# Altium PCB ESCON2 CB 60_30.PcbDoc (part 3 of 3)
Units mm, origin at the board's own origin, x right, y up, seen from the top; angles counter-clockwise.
Board outline 93.5 x 46 mm, 8 copper layers (Top Side, Inner Layer 1, Inner Layer 2, Inner Layer 3, Inner Layer 4, Inner Layer 5, Inner Layer 6, Bottom Side), stack 1.485 mm thick; 144 components, 77 nets, 473 pads, 3049 vias.
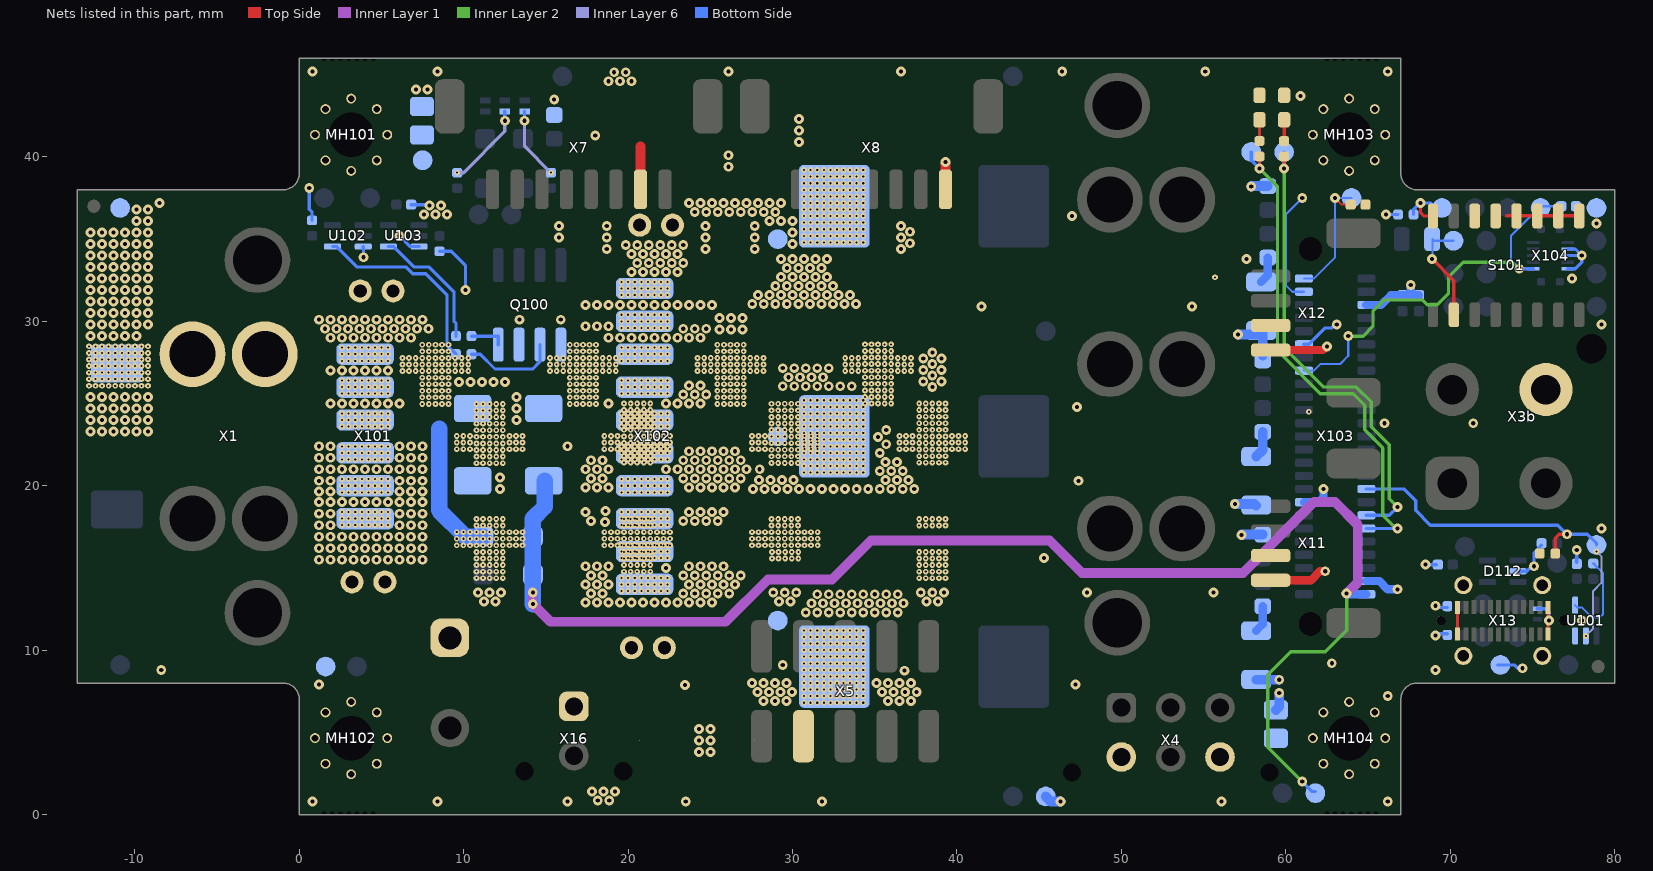
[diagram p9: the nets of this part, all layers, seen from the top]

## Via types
v1: diameter 0.35, hole 0.125, Inner Layer 6 to Bottom Side, tented both sides, 1246 vias
v2: diameter 0.6, hole 0.25, Top Side to Bottom Side, 953 vias
v3: diameter 0.35, hole 0.125, Top Side to Inner Layer 1, tented both sides, 790 vias
v4: diameter 0.6, hole 0.25, Top Side to Bottom Side, tented bottom, 58 vias
v5: diameter 0.6, hole 0.25, Top Side to Bottom Side, tented top, 2 vias

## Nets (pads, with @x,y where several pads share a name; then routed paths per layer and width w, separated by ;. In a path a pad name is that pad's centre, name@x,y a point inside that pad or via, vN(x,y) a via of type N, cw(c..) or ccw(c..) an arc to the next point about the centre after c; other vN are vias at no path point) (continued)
GND: C101.2 C102.2 C103.2 C104.2 C105.2 C106.2 C108.2 C110.2 C112.1 C113.1 C114.1 C115.1 C116.1 C117.1 C118.1 C119.1 C120.2 C121.2 C122.1 C123.1 C124.1 D101.2 D104.2 D106.1 D112.2 D113.1 D114.1 DS101.1 DS102.1 Q100.1 Q100.3 R102.1 R103.1 R105.1 R107.2 R108.2 R117.1 R118.1 R119.1 R120.1 R121.1 S101.1 S101.2 S101.3 S101.4 S101.5 S101.6 TP101.1 TP116.1 TP125.1 TP149.1 U101.3 U102.3 U103.3 X1.1 X2.1 X4.4 X5.3 X7.7 X8.7 X11.3 X12.3 X13.A1 X13.A12 X13.B1 X13.B12 X16.1 X101.0a X101.1 X101.2 X101.3 X103.3 X103.16 X103.40 X103.45 X104.3 X104.5 X104.9 | length 54.3
  Top Side w0.2: X13.A12@70.45,10.965 X13.A12@70.45,10.995 X13.B1@70.45,12.605 X13.B1@70.45,12.635 ; 73.425,36.425 76.575,36.425 77.827,36.425 S101.1@77.845,36.407 ; X13.A1@75.95,10.965 X13.A1@75.95,10.995 X13.B12@75.95,12.605 X13.B12@75.95,12.635
  Top Side w0.6: X7.7@20.75,38.025 20.75,40.65 ; X8.7@39.3,37.925 X8.7@39.3,38.025 v2@39.3,39.6
  Bottom Side w0.2: v2(0.6,38.1) 0.6,36.825 0.775,36.65 R119.1@0.775,36.14 ; U102.3@3.885,34.55 3.885,34.365 3.9,34.35 v2(3.9,33.9) ; v2(6.1,35.2) 6.75,34.55 U103.3@7.285,34.55 ; C122.1@6.8,37.1 v2@8,37.1 ; R120.1@8.525,34.255 9.245,34.255 10.1,33.4 v2(10.1,31.9) ; X103.40@61.1,28.6 61.4,28.6 62.4,29.6 62.8,29.6 63,29.8 v2(63.1,29.8) ; v2(66.1,36.5) R117.1@66.83,36.5 ; v2(68.5,15.2) C112.1@69.15,15.2 ; v2@69.1,11 R108.2@69.83,11 ; v2@69.1,12.6 R107.2@69.83,12.6 ; TP116.1@72.9,9.1 TP116.1@73.05,9.1 73.9,9.1 74.1,8.9 v2(74.4,8.9) ; D112.2@74.135,14.8 74.655,14.8 74.955,15.1 v2(75.1,15.1) 75.1,15.94 R118.1@75.56,16.4 ; D106.1@75.3,12.525 75.775,12.525 76,12.3 v2(76,11.8) ; X104.9@77.145,33.2 77.6,33.2 78,33.6 v2(78,34) ; X104.5@77.145,34 77.53,34 v2(78,34) ; X104.3@77.145,34.4 77.6,34.4 v2(78,34) ; C116.1@77.7,15.35 v2(77.7,16.1)
  Bottom Side w0.5: X103.16@61.1,19 62,19 62.3,19.3 v2(62.3,19.8) ; X103.3@64.9,14.2 65.7,14.2 66.2,13.7 v2(66.8,13.7) ; X103.45@64.9,31 65.45,31 65.8,31 66.385,31.585 D114.1@67.1,31.585 D113.1@68.1,31.585 67.6,31.585 v2(67.6,32.2)
  Bottom Side w0.6: TP125.1@45.4,1.1 45.7,0.8 v4(46.3,0.8) ; v2@56.912,18.888 58.108,18.888 R103.1@58.188,18.808 ; v2(57.1,29.2) 58.26,29.2 R105.1@58.5,29.44 58.6,29.34 C114.1@58.6,27.925 ; v2@57.325,17.025 C113.1@58.6,17.025 ; v2(57.9,38.2) 57.925,38.225 C115.1@58.9,38.225 ; R102.1@58.22,8.2 v2(59.6,8.2) ; C118.1@59.4,6.365 59.6,6.565 v2(59.6,7.4)
  other v1: 2.6,17.6 3,17.6 3.4,17.6 3.8,17.6 4.2,17.6 4.6,17.6 5,17.6 5.4,17.6 2.6,18 3,18 3.4,18 3.8,18 4.2,18 4.6,18 5,18 5.4,18 2.6,18.4 3,18.4 3.4,18.4 3.8,18.4 4.2,18.4 4.6,18.4 5,18.4 5.4,18.4 2.6,19.6 3,19.6 3.4,19.6 3.8,19.6 4.2,19.6 4.6,19.6 5,19.6 5.4,19.6 2.6,20 3,20 3.4,20 3.8,20 4.2,20 4.6,20 5,20 5.4,20 2.6,20.4 3,20.4 3.4,20.4 3.8,20.4 4.2,20.4 4.6,20.4 5,20.4 5.4,20.4 2.6,21.6 3,21.6 3.4,21.6 3.8,21.6 4.2,21.6 4.6,21.6 5,21.6 5.4,21.6 2.6,22 3,22 3.4,22 3.8,22 4.2,22 4.6,22 5,22 5.4,22 2.6,22.4 3,22.4 3.4,22.4 3.8,22.4 4.2,22.4 4.6,22.4 5,22.4 5.4,22.4
  other v2: 0.8,0.8 8.4,0.8 16.3,0.8 23.5,0.8 31.8,0.8 56.1,0.8 66.2,0.8 24.3,3.8 25,3.8 24.3,4.5 25,4.5 24.3,5.2 25,5.2 66.2,7.2 23.463,7.871 1.2,7.9 47.2,7.9 36.8,8.75 -8.4,8.8 69.1,8.8 29.4,9.1 62.8,9.2 69.1,10.9 78,11.8 69.1,12.7 11.225,12.95 11.925,12.95 29.175,12.95 29.875,12.95 38.15,12.95 38.85,12.95 10.875,13.5 11.575,13.5 12.275,13.5 28.825,13.5 29.525,13.5 30.225,13.5 37.8,13.5 38.5,13.5 39.2,13.5 47.9,13.5 55.6,13.5 1.2,15.5 1.9,15.5 2.6,15.5 3.3,15.5 4,15.5 4.7,15.5 5.4,15.5 6.1,15.5 6.8,15.5 7.5,15.5 45.3,15.6 1.2,16.2 1.9,16.2 2.6,16.2 3.3,16.2 4,16.2 4.7,16.2 5.4,16.2 6.1,16.2 6.8,16.2 7.5,16.2 1.2,16.9 1.9,16.9 2.6,16.9 3.3,16.9 4,16.9 4.7,16.9 5.4,16.9 6.1,16.9 6.8,16.9 7.5,16.9 57.3,17 79.2,17.4 1.2,17.6 6.8,17.6 7.5,17.6 18.6,17.8 1.2,18.3 6.8,18.3 7.5,18.3 18.626,18.462 56.9,18.9 1.2,19 1.9,19 6.1,19 6.8,19 7.5,19 1.2,19.65 6.8,19.65 7.5,19.65 12.2,19.8 1.2,20.3 6.8,20.3 7.5,20.3 47.4,20.3 12.2,20.5 1.2,21 6.1,21 6.8,21 7.5,21 1.2,21.7 6.8,21.7 7.5,21.7 1.2,22.4 6.8,22.4 7.5,22.4 16.3,22.4 66,23.8 71.4,23.8 13.2,24 13.2,24.7 47.3,24.8 13.2,25.4 79.2,29.8 13.4,30.1 15.9,30.1 41.5,30.9 54.3,30.9 77.4,32.6 57.6,33.8 18.7,34.4 24.7,34.4 27.7,34.4 36.6,34.4 37.15,34.75 15.8,35.1 18.7,35.1 24.7,35.1 27.7,35.1 36.6,35.1 37.15,35.45 15.8,35.8 18.7,35.8 24.7,35.8 27.7,35.8 36.6,35.8 47,36.4 7.575,36.5 8.275,36.5 8.975,36.5 7.925,37.05 8.625,37.05 -8.5,37.2 26.1,39.4 39.3,39.7 26.1,40.1 30.4,40.9 18,41.3 30.4,41.6 30.4,42.3 15.5,43.5 60.9,43.7 7.1,44.1 7.8,44.1 0.8,45.2 8.4,45.2 26.1,45.2 36.6,45.2 46.4,45.2 55.1,45.2 66.2,45.2
  other v3: 10.775,14.375 11.175,14.375 11.575,14.375 11.975,14.375 12.375,14.375 37.7,14.375 38.1,14.375 38.5,14.375 38.9,14.375 39.3,14.375 10.775,14.775 11.175,14.775 11.575,14.775 11.975,14.775 12.375,14.775 19.75,14.775 20.15,14.775 20.55,14.775 20.95,14.775 21.35,14.775 37.7,14.775 38.1,14.775 38.5,14.775 38.9,14.775 39.3,14.775 10.775,15.175 11.175,15.175 11.575,15.175 11.975,15.175 12.375,15.175 19.75,15.175 20.15,15.175 20.55,15.175 20.95,15.175 21.35,15.175 37.7,15.175 38.1,15.175 38.5,15.175 38.9,15.175 39.3,15.175 10.775,15.575 11.175,15.575 11.575,15.575 11.975,15.575 12.375,15.575 19.75,15.575 20.15,15.575 20.55,15.575 20.95,15.575 21.35,15.575 28.75,15.575 29.15,15.575 29.55,15.575 29.95,15.575 30.35,15.575 37.7,15.575 38.1,15.575 38.5,15.575 38.9,15.575 39.3,15.575 10.775,15.975 11.175,15.975 11.575,15.975 11.975,15.975 12.375,15.975 19.75,15.975 20.15,15.975 20.55,15.975 20.95,15.975 21.35,15.975 28.75,15.975 29.15,15.975 29.55,15.975 29.95,15.975 30.35,15.975 37.7,15.975 38.1,15.975 38.5,15.975 38.9,15.975 39.3,15.975 9.575,16.375 9.975,16.375 10.375,16.375 10.775,16.375 11.175,16.375 11.575,16.375 11.975,16.375 12.375,16.375 12.775,16.375 13.175,16.375 13.575,16.375 18.55,16.375 18.95,16.375 19.35,16.375 19.75,16.375 20.15,16.375 20.55,16.375 20.95,16.375 21.35,16.375 21.75,16.375 22.15,16.375 22.55,16.375 27.525,16.375 27.925,16.375 28.325,16.375 28.725,16.375 29.125,16.375 29.525,16.375 29.925,16.375 30.325,16.375 30.725,16.375 31.125,16.375 31.525,16.375 9.575,16.775 9.975,16.775 10.375,16.775 10.775,16.775 11.175,16.775 11.575,16.775 11.975,16.775 12.375,16.775 12.775,16.775 13.175,16.775 13.575,16.775 18.55,16.775 18.95,16.775 19.35,16.775 19.75,16.775 20.15,16.775 20.55,16.775 20.95,16.775 21.35,16.775 21.75,16.775 22.15,16.775 22.55,16.775 27.525,16.775 27.925,16.775 28.325,16.775 28.725,16.775 29.125,16.775 29.525,16.775 29.925,16.775 30.325,16.775 30.725,16.775 31.125,16.775 31.525,16.775 9.575,17.175 9.975,17.175 10.375,17.175 10.775,17.175 11.175,17.175 11.575,17.175 11.975,17.175 12.375,17.175 12.775,17.175 13.175,17.175 13.575,17.175 18.55,17.175 18.95,17.175 19.35,17.175 19.75,17.175 20.15,17.175 20.55,17.175 20.95,17.175 21.35,17.175 21.75,17.175 22.15,17.175 22.55,17.175 27.525,17.175 27.925,17.175 28.325,17.175 28.725,17.175 29.125,17.175 29.525,17.175 29.925,17.175 30.325,17.175 30.725,17.175 31.125,17.175 31.525,17.175 10.775,17.575 11.175,17.575 11.575,17.575 11.975,17.575 12.375,17.575 19.75,17.575 20.15,17.575 20.55,17.575 20.95,17.575 21.35,17.575 28.725,17.575 29.125,17.575 29.525,17.575 29.925,17.575 30.325,17.575 37.7,17.575 38.1,17.575 38.5,17.575 38.9,17.575 39.3,17.575 10.775,17.975 11.175,17.975 11.575,17.975 11.975,17.975 12.375,17.975 19.75,17.975 20.15,17.975 20.55,17.975 20.95,17.975 21.35,17.975 28.725,17.975 29.125,17.975 29.525,17.975 29.925,17.975 30.325,17.975 37.7,17.975 38.1,17.975 38.5,17.975 38.9,17.975 39.3,17.975 61.4,24.5 55.7,32.675
  other v4: 1.9,17.6 6.1,17.6 1.9,18.3 6.1,18.3 2.6,19 3.3,19 4,19 4.7,19 5.4,19 1.9,19.65 6.1,19.65 1.9,20.3 6.1,20.3 1.9,21 2.6,21 3.3,21 4,21 4.7,21 5.4,21 1.9,21.7 6.1,21.7 1.9,22.4 6.1,22.4 78.9,35.95
LED_Axis_gn: R110.1 TP142.1 X103.13 | length 28.5
  Top Side w0.2: v2(59.9,39.3) R110.1@59.9,40.03
  Inner Layer 2 w0.2: v2(59.9,39.3) 59.9,28.4 62.3,26 64.3,26 65.2,25.1 65.2,23.6 66.3,22.5 66.3,19.2 v2(66.8,18.7)
  Bottom Side w0.2: v2(59.9,39.3) TP142.1@59.9,40.3 ; X103.13@64.9,18.2 66.3,18.2 v2(66.8,18.7)
LED_Axis_rd: R109.1 TP141.1 X103.11 | length 30.4
  Top Side w0.2: v2(58.4,39.3) R109.1@58.4,40.03
  Inner Layer 2 w0.2: v2(58.4,39.3) 59.5,38.2 59.5,28.2 62.1,25.6 64.1,25.6 64.8,24.9 64.8,23.4 65.9,22.3 65.9,18.2 66.7,17.4 v2(66.8,17.4)
  Bottom Side w0.2: TP141.1@57.9,40.3 57.9,39.8 v2(58.4,39.3) ; X103.11@64.9,17.4 v2(66.8,17.4)
NetC107_1: C107.1 R102.2 | length 1.7
  Bottom Side w0.5: R102.2@58.2,11.18 58.6,11.58 C107.1@58.6,12.675
NetC109_1: C109.1 R103.2 | length 1.7
  Bottom Side w0.6: R103.2@58.2,21.78 58.6,22.18 C109.1@58.6,23.275
NetC111_1: C111.1 R105.2 | length 1.6
  Bottom Side w0.5: R105.2@58.5,32.4 58.9,32.8 C111.1@58.9,33.875
NetD108_1: D108.1 R115.2 | length 4.4
  Inner Layer 6 w0.2: v2(13.7,42.2) 13.7,40.64 v1(15.3,39.04)
  Bottom Side w0.2: v2(13.7,42.2) D108.1@13.7,42.775
NetD109_1: D109.1 R116.2 | length 5.2
  Inner Layer 6 w0.2: v1(9.6,39.04) 9.99,39.04 12.5,41.55 v2(12.5,42.2)
  Bottom Side w0.2: v2(12.5,42.2) D109.1@12.5,42.775
NetDS101_2: DS101.2 R109.2 | length 1.3
  Top Side w0.2: R109.2@58.4,40.97 58.4,41.265 DS101.2@58.4,42.255
NetDS102_2: DS102.2 R110.2 | length 1.3
  Top Side w0.2: R110.2@59.9,40.97 59.9,41.265 DS102.2@59.9,42.255
NetQ100_2: Q100.2 R112.2 | length 5.8
  Bottom Side w0.2: R112.2@10.47,28 11,28 11.9,27.1 14.19,27.1 14.635,27.545 Q100.2@14.635,28.58
NetQ100_4: Q100.4 R114.2 | length 2.1
  Bottom Side w0.2: R114.2@10.47,29.1 12.095,29.1 Q100.4@12.095,28.58
NetR104_1: R104.1 S101.10 TP132.1 | length 6.5
  Top Side w0.2: v2(68.9,33.8) 70.225,32.475 S101.10@70.225,30.393
  Bottom Side w0.125: v2(68.9,33.8) 68.925,33.825 68.925,35 69.025,34.9 TP132.1@70.2,34.9
NetR111_2: R111.2 U101.4 | length 5.4
  Bottom Side w0.125: U101.4@77.6,12.735 77.6,12.721 77.72,12.601 78.003,12.601 78.604,12 79.1,12 79.3,12.2 79.3,14.67 R111.2@78.731,15.239 ; R111.2@78.7,15.27 R111.2@78.763,15.27
NetR112_1: R112.1 U102.4 | length 12
  Bottom Side w0.2: U102.4@2.015,34.55 2.275,34.55 3.525,33.3 6.5,33.3 6.9,32.9 7.7,32.9 8.975,31.625 8.975,28.555 R112.1@9.53,28
NetR114_1: R114.1 U103.4 | length 7.9
  Bottom Side w0.2: U103.4@5.415,34.55 5.75,34.55 7,33.3 7.9,33.3 9.4,31.8 9.4,30 9.53,29.87 R114.1@9.53,29.1
NetR117_2: R117.2 S101.8 TP134.1 | length 3.4
  Top Side w0.2: v2(68.2,37.2) 68.2,36.6 68.393,36.407 S101.8@68.955,36.407
  Bottom Side w0.2: R117.2@67.77,36.5 67.77,36.81 68.16,37.2 v2(68.2,37.2) 68.8,37.2 TP134.1@69.1,36.9
S2_Clock: R121.2 TP144.1 U101.2 X103.17 | length 23.2
  Top Side w0.2: R121.2@76.395,15.875 76.395,16.82 76.625,17.05 v2(77.1,17.05)
  Inner Layer 6 w0.125: v1(78.25,10.865) 78.7,11.315 78.7,13.6 79.2,14.1 79.2,15.7 v1(78.9,16)
  Bottom Side w0.2: X103.17@64.9,19.8 67.2,19.8 67.9,19.1 67.9,18.5 68.8,17.6 76.55,17.6 v2(77.1,17.05) 78.35,17.05 78.9,16.5 TP144.1@78.9,16.4
SGND: C117.2 C118.2 MH101.2 MH101.3 MH101.4 MH101.5 MH101.6 MH101.7 MH101.8 MH101.9 MH102.2 MH102.3 MH102.4 MH102.5 MH102.6 MH102.7 MH102.8 MH102.9 MH103.2 MH103.3 MH103.4 MH103.5 MH103.6 MH103.7 MH103.8 MH103.9 MH104.2 MH104.3 MH104.4 MH104.5 MH104.6 MH104.7 MH104.8 MH104.9 TP153.1 X3b.4 X4.6 X11.4 X12.4 X13.S1 X13.S2 X13.S3 X13.S4 | length 7.2
  Top Side w0.5: X11.4@59.025,14.25 61.525,14.25 62.075,14.8 v2(62.4,14.8) ; X12.4@59.025,28.25 62.25,28.25 v2@62.5,28.5
  other v2: 62.5,28.475
SYS_/Reset: C123.2 TP154.1 X103.36 X104.10 | length 24.9
  Inner Layer 2 w0.2: v2(63.8,29.1) 64.7,29.1 65.3,29.7 65.3,30.6 66,31.3 68.3,31.3 68.6,31 69.2,31 69.9,31.7 69.9,32.7 70.8,33.6 73.8,33.6 v2(74.2,33.2)
  Bottom Side w0.125: X103.36@61.1,27 61.7,27 62.1,27.4 63.3,27.4 63.8,27.9 v2(63.8,29.1) ; v2(74.2,33.2) 73.7,33.7 73.7,35.207 TP154.1@75.446,36.954 ; TP154.1@75.5,36.9 75.6,37 C123.2@76.75,37
  Bottom Side w0.2: v2(74.2,33.2) X104.10@75.055,33.2
U: L101.2 TP138.1 X102.0a X102.1 X102.2 X102.3
  other v1: 30.7,6.8 31.1,6.8 31.5,6.8 31.9,6.8 32.3,6.8 32.7,6.8 33.1,6.8 33.5,6.8 33.9,6.8 34.3,6.8 30.7,7.2 31.1,7.2 31.5,7.2 31.9,7.2 32.3,7.2 32.7,7.2 33.1,7.2 33.5,7.2 33.9,7.2 34.3,7.2 30.7,7.6 31.1,7.6 31.5,7.6 31.9,7.6 32.3,7.6 32.7,7.6 33.1,7.6 33.5,7.6 33.9,7.6 34.3,7.6 30.7,8 31.1,8 31.5,8 31.9,8 32.3,8 32.7,8 33.1,8 33.5,8 33.9,8 34.3,8 30.7,8.4 31.1,8.4 31.5,8.4 31.9,8.4 32.3,8.4 32.7,8.4 33.1,8.4 33.5,8.4 33.9,8.4 34.3,8.4 30.7,8.8 31.1,8.8 31.5,8.8 31.9,8.8 32.3,8.8 32.7,8.8 33.1,8.8 33.5,8.8 33.9,8.8 34.3,8.8 30.7,9.2 31.1,9.2 31.5,9.2 31.9,9.2 32.3,9.2 32.7,9.2 33.1,9.2 33.5,9.2 33.9,9.2 34.3,9.2 30.7,9.6 31.1,9.6 31.5,9.6 31.9,9.6 32.3,9.6 32.7,9.6 33.1,9.6 33.5,9.6 33.9,9.6 34.3,9.6 30.7,10 31.1,10 31.5,10 31.9,10 32.3,10 32.7,10 33.1,10 33.5,10 33.9,10 34.3,10 30.7,10.4 31.1,10.4 31.5,10.4 31.9,10.4 32.3,10.4 32.7,10.4 33.1,10.4 33.5,10.4 33.9,10.4 34.3,10.4 30.7,10.8 31.1,10.8 31.5,10.8 31.9,10.8 32.3,10.8 32.7,10.8 33.1,10.8 33.5,10.8 33.9,10.8 34.3,10.8 30.7,11.2 31.1,11.2 31.5,11.2 31.9,11.2 32.3,11.2 32.7,11.2 33.1,11.2 33.5,11.2 33.9,11.2 34.3,11.2 19.6,13.6 20,13.6 20.4,13.6 20.8,13.6 21.2,13.6 21.6,13.6 22,13.6 22.4,13.6 19.6,14 20,14 20.4,14 20.8,14 21.2,14 21.6,14 22,14 22.4,14 19.6,14.4 20,14.4 20.4,14.4 20.8,14.4 21.2,14.4 21.6,14.4 22,14.4 22.4,14.4 19.6,15.6 20,15.6 20.4,15.6 20.8,15.6 21.2,15.6 21.6,15.6 22,15.6 22.4,15.6 19.6,16 20,16 20.4,16 20.8,16 21.2,16 21.6,16 22,16 22.4,16 19.6,16.4 20,16.4 20.4,16.4 20.8,16.4 21.2,16.4 21.6,16.4 22,16.4 22.4,16.4 19.6,17.6 20,17.6 20.4,17.6 20.8,17.6 21.2,17.6 21.6,17.6 22,17.6 22.4,17.6 19.6,18 20,18 20.4,18 20.8,18 21.2,18 21.6,18 22,18 22.4,18 19.6,18.4 20,18.4 20.4,18.4 20.8,18.4 21.2,18.4 21.6,18.4 22,18.4 22.4,18.4
  other v2: 28.225,6.9 28.925,6.9 29.625,6.9 35.8,6.9 36.5,6.9 37.2,6.9 27.875,7.45 28.575,7.45 29.275,7.45 29.975,7.45 35.45,7.45 36.15,7.45 36.85,7.45 37.55,7.45 27.525,8 28.225,8 28.925,8 29.625,8 35.1,8 35.8,8 36.5,8 37.2,8 30.8,12.3 31.5,12.3 32.2,12.3 32.9,12.3 33.6,12.3 34.3,12.3 35,12.3 35.7,12.3 36.4,12.3 31.15,12.85 31.85,12.85 32.55,12.85 33.25,12.85 33.95,12.85 34.65,12.85 35.35,12.85 36.05,12.85 36.75,12.85 17.4,12.9 18.1,12.9 18.8,12.9 19.5,12.9 20.2,12.9 20.9,12.9 21.6,12.9 22.3,12.9 23,12.9 23.7,12.9 24.4,12.9 25.1,12.9 31.5,13.4 32.2,13.4 32.9,13.4 33.6,13.4 34.3,13.4 35,13.4 35.7,13.4 36.4,13.4 17.75,13.45 18.45,13.45 23.35,13.45 24.05,13.45 24.75,13.45 25.45,13.45 26.15,13.45 17.4,14 18.1,14 18.8,14 23.7,14 24.4,14 25.1,14 25.8,14 26.5,14 17.75,14.55 18.45,14.55 23.35,14.55 24.05,14.55 24.75,14.55 25.45,14.55 26.15,14.55 26.85,14.55 17.4,15.1 18.1,15.1 18.8,15.1 23.7,15.1 24.4,15.1 25.1,15.1 25.8,15.1 17.75,17.85 23.35,17.85 24.05,17.85 24.75,17.85 25.45,17.85 17.4,18.4 23.7,18.4 24.4,18.4 25.1,18.4 25.8,18.4
  other v4: 22.3,15
UART_RxD: C124.2 TP155.1 TPM2.1 X103.50 | length 8.2
  Top Side w0.125: v2(63,37.5) 63.4,37.1 C124.2@63.95,37.1
  Bottom Side w0.125: X103.50@61.1,32.6 61.7,32.6 63,33.9 v2(63,37.5) TP155.1@64,37.5
UART_TxD: TPM1.1 X103.48 | length 7
  Bottom Side w0.125: v2(61,37.5) 60,36.5 60,32.2 60.4,31.8 X103.48@61.1,31.8
V: L102.2 TP139.1 X102.4 X102.5 X102.6 X102.7
  other v1: 19.6,19.6 20,19.6 20.4,19.6 20.8,19.6 21.2,19.6 21.6,19.6 22,19.6 22.4,19.6 19.6,20 20,20 20.4,20 20.8,20 21.2,20 21.6,20 22,20 22.4,20 19.6,20.4 20,20.4 20.4,20.4 20.8,20.4 21.2,20.4 21.6,20.4 22,20.4 22.4,20.4 30.7,20.8 31.1,20.8 31.5,20.8 31.9,20.8 32.3,20.8 32.7,20.8 33.1,20.8 33.5,20.8 33.9,20.8 34.3,20.8 30.7,21.2 31.1,21.2 31.5,21.2 31.9,21.2 32.3,21.2 32.7,21.2 33.1,21.2 33.5,21.2 33.9,21.2 34.3,21.2 19.6,21.6 20,21.6 20.4,21.6 20.8,21.6 21.2,21.6 21.6,21.6 22,21.6 22.4,21.6 30.7,21.6 31.1,21.6 31.5,21.6 31.9,21.6 32.3,21.6 32.7,21.6 33.1,21.6 33.5,21.6 33.9,21.6 34.3,21.6 19.6,22 20,22 20.4,22 20.8,22 21.2,22 21.6,22 22,22 22.4,22 30.7,22 31.1,22 31.5,22 31.9,22 32.3,22 32.7,22 33.1,22 33.5,22 33.9,22 34.3,22 19.6,22.4 20,22.4 20.4,22.4 20.8,22.4 21.2,22.4 21.6,22.4 22,22.4 22.4,22.4 30.7,22.4 31.1,22.4 31.5,22.4 31.9,22.4 32.3,22.4 32.7,22.4 33.1,22.4 33.5,22.4 33.9,22.4 34.3,22.4 30.7,22.8 31.1,22.8 31.5,22.8 31.9,22.8 32.3,22.8 32.7,22.8 33.1,22.8 33.5,22.8 33.9,22.8 34.3,22.8 30.7,23.2 31.1,23.2 31.5,23.2 31.9,23.2 32.3,23.2 32.7,23.2 33.1,23.2 33.5,23.2 33.9,23.2 34.3,23.2 19.6,23.6 20,23.6 20.4,23.6 20.8,23.6 21.2,23.6 21.6,23.6 22,23.6 22.4,23.6 30.7,23.6 31.1,23.6 31.5,23.6 31.9,23.6 32.3,23.6 32.7,23.6 33.1,23.6 33.5,23.6 33.9,23.6 34.3,23.6 19.6,24 20,24 20.4,24 20.8,24 21.2,24 21.6,24 22,24 22.4,24 30.7,24 31.1,24 31.5,24 31.9,24 32.3,24 32.7,24 33.1,24 33.5,24 33.9,24 34.3,24 19.6,24.4 20,24.4 20.4,24.4 20.8,24.4 21.2,24.4 21.6,24.4 22,24.4 22.4,24.4 30.7,24.4 31.1,24.4 31.5,24.4 31.9,24.4 32.3,24.4 32.7,24.4 33.1,24.4 33.5,24.4 33.9,24.4 34.3,24.4 30.7,24.8 31.1,24.8 31.5,24.8 31.9,24.8 32.3,24.8 32.7,24.8 33.1,24.8 33.5,24.8 33.9,24.8 34.3,24.8 30.7,25.2 31.1,25.2 31.5,25.2 31.9,25.2 32.3,25.2 32.7,25.2 33.1,25.2 33.5,25.2 33.9,25.2 34.3,25.2 19.6,25.6 20,25.6 20.4,25.6 20.8,25.6 21.2,25.6 21.6,25.6 22,25.6 22.4,25.6 19.6,26 20,26 20.4,26 20.8,26 21.2,26 21.6,26 22,26 22.4,26 19.6,26.4 20,26.4 20.4,26.4 20.8,26.4 21.2,26.4 21.6,26.4 22,26.4 22.4,26.4
  other v2: 27.6,19.8 28.3,19.8 29,19.8 29.7,19.8 30.4,19.8 31.1,19.8 31.8,19.8 32.5,19.8 33.2,19.8 33.9,19.8 34.6,19.8 35.3,19.8 36,19.8 36.7,19.8 37.4,19.8 17.4,19.9 18.1,19.9 18.8,19.9 23.7,19.9 24.4,19.9 25.1,19.9 25.8,19.9 26.5,19.9 27.95,20.35 28.65,20.35 29.35,20.35 30.05,20.35 35.65,20.35 36.35,20.35 37.05,20.35 17.75,20.45 18.45,20.45 23.35,20.45 24.05,20.45 24.75,20.45 25.45,20.45 26.15,20.45 26.85,20.45 35.3,20.9 36,20.9 36.7,20.9 17.4,21 18.1,21 18.8,21 23,21 23.7,21 24.4,21 25.1,21 25.8,21 26.5,21 27.2,21 28,21 35.65,21.45 36.35,21.45 17.75,21.55 18.45,21.55 23.35,21.55 24.05,21.55 24.75,21.55 25.45,21.55 26.15,21.55 26.85,21.55 35.3,22 23.7,22.1 24.4,22.1 25.1,22.1 25.8,22.1 26.5,22.1 35.7,22.525 35.2,22.975 35.7,23.4 18.8,25 23,25 23.7,25 24.4,25 23.35,25.55 24.05,25.55 24.75,25.55 29.4,26.05 30.1,26.05 30.8,26.05 31.5,26.05 32.2,26.05 32.9,26.05 33.6,26.05 23.7,26.1 24.4,26.1 29.75,26.6 30.45,26.6 31.15,26.6 31.85,26.6 29.4,27.15 30.1,27.15 30.8,27.15 31.5,27.15 32.2,27.15
  other v4: 22.3,21 22.3,25
VL: D102.1 D103.1 D104.1 TP106.1 X103.1 | length 86.6
  Inner Layer 1 w0.6: v2(14.2,13.5) v2(14.2,12.8) 15.275,11.725 25.925,11.725 28.5,14.3 32.4,14.3 34.775,16.675 45.625,16.675 47.6,14.7 57.4,14.7 61.7,19 63,19 64.375,17.625 64.375,14.125 v2(63.7,13.45)
  Inner Layer 2 w0.2: v2(61,2) 58.9,4.1 58.9,8.5 60.3,9.9 62.4,9.9 63.7,11.2 v2(63.7,13.45)
  Bottom Side w0.2: v2(61,2) 61.6,1.4 TP106.1@61.8,1.4
  Bottom Side w0.5: v2(63.7,13.45) 63.75,13.4 X103.1@64.9,13.4
  Bottom Side w1: v2(14.2,12.8) v2(14.2,13.5) ; v2@14.205,13.5 D102.1@14.205,14.6 D103.1@14.205,16.9 14.205,18.005 14.92,18.72 D104.1@14.92,20.3
VP: C101.1 C102.1 C103.1 C104.1 C105.1 C106.1 C108.1 C110.1 C120.1 C121.1 D101.1 D103.2 F101.2 TP104.1 X101.0b X101.4 X101.5 X101.6 | length 8.3
  Bottom Side w1: 8.5,23.473 8.5,18.5 10.1,16.9 D103.2@11.195,16.9
  other v1: 2.6,23.6 3,23.6 3.4,23.6 3.8,23.6 4.2,23.6 4.6,23.6 5,23.6 5.4,23.6 2.6,24 3,24 3.4,24 3.8,24 4.2,24 4.6,24 5,24 5.4,24 2.6,24.4 3,24.4 3.4,24.4 3.8,24.4 4.2,24.4 4.6,24.4 5,24.4 5.4,24.4 2.6,25.6 3,25.6 3.4,25.6 3.8,25.6 4.2,25.6 4.6,25.6 5,25.6 5.4,25.6 2.6,26 3,26 3.4,26 3.8,26 4.2,26 4.6,26 5,26 5.4,26 -12.8,26.08 -12.4,26.08 -12,26.08 -11.6,26.08 -11.2,26.08 -10.8,26.08 -10.4,26.08 -10,26.08 -9.6,26.08 -9.2,26.08 2.6,26.4 3,26.4 3.4,26.4 3.8,26.4 4.2,26.4 4.6,26.4 5,26.4 5.4,26.4 -12.8,26.48 -12.4,26.48 -12,26.48 -11.6,26.48 -11.2,26.48 -10.8,26.48 -10.4,26.48 -10,26.48 -9.6,26.48 -9.2,26.48 -12.8,26.88 -12.4,26.88 -12,26.88 -11.6,26.88 -11.2,26.88 -10.8,26.88 -10.4,26.88 -10,26.88 -9.6,26.88 -9.2,26.88 -12.8,27.28 -12.4,27.28 -12,27.28 -11.6,27.28 -11.2,27.28 -10.8,27.28 -10.4,27.28 -10,27.28 -9.6,27.28 -9.2,27.28 2.6,27.6 3,27.6 3.4,27.6 3.8,27.6 4.2,27.6 4.6,27.6 5,27.6 5.4,27.6 -12.8,27.68 -12.4,27.68 -12,27.68 -11.6,27.68 -11.2,27.68 -10.8,27.68 -10.4,27.68 -10,27.68 -9.6,27.68 -9.2,27.68 2.6,28 3,28 3.4,28 3.8,28 4.2,28 4.6,28 5,28 5.4,28 -12.8,28.08 -12.4,28.08 -12,28.08 -11.6,28.08 -11.2,28.08 -10.8,28.08 -10.4,28.08 -10,28.08 -9.6,28.08 -9.2,28.08 2.6,28.4 3,28.4 3.4,28.4 3.8,28.4 4.2,28.4 4.6,28.4 5,28.4 5.4,28.4 -12.8,28.48 -12.4,28.48 -12,28.48 -11.6,28.48 -11.2,28.48 -10.8,28.48 -10.4,28.48 -10,28.48 -9.6,28.48 -9.2,28.48
  other v2: 18.15,0.85 18.85,0.85 17.8,1.4 18.5,1.4 19.2,1.4 -12.7,23.3 -12,23.3 -11.3,23.3 -10.6,23.3 -9.9,23.3 -9.2,23.3 -12.7,24 -12,24 -11.3,24 -10.6,24 -9.9,24 -9.2,24 -12.7,24.7 -12,24.7 -11.3,24.7 -10.6,24.7 -9.9,24.7 -9.2,24.7 1.9,25 6.1,25 -12.7,25.4 -12,25.4 -11.3,25.4 -10.6,25.4 -9.9,25.4 -9.2,25.4 38.5,26 11.1,26.3 11.8,26.3 12.5,26.3 37.95,26.35 39.05,26.35 38.5,26.7 1.9,27 37.95,27.05 39.05,27.05 38.5,27.4 37.95,27.75 39.05,27.75 38.5,28.1 1.9,29 6.1,29 6.8,29 -12.7,29.1 -12,29.1 -11.3,29.1 -10.6,29.1 -9.9,29.1 25.55,29.5 26.25,29.5 26.95,29.5 1.55,29.55 2.25,29.55 2.95,29.55 3.65,29.55 4.35,29.55 5.05,29.55 5.75,29.55 6.45,29.55 7.15,29.55 7.85,29.55 -12.7,29.8 -12,29.8 -11.3,29.8 -10.6,29.8 -9.9,29.8 -9.2,29.8 1.2,30.1 1.9,30.1 2.6,30.1 3.3,30.1 4,30.1 4.7,30.1 5.4,30.1 6.1,30.1 6.8,30.1 7.5,30.1 25.55,30.2 26.25,30.2 26.95,30.2 -12.7,30.5 -12,30.5 -11.3,30.5 -10.6,30.5 -9.9,30.5 -9.2,30.5 -12.7,31.2 -12,31.2 -11.3,31.2 -10.6,31.2 -9.9,31.2 -9.2,31.2 -12.7,31.9 -12,31.9 -11.3,31.9 -10.6,31.9 -9.9,31.9 -9.2,31.9 -12.7,32.6 -12,32.6 -11.3,32.6 -10.6,32.6 -9.9,32.6 -9.2,32.6 -12.7,33.3 -12,33.3 -11.3,33.3 -10.6,33.3 -9.9,33.3 -9.2,33.3 -12.7,34 -12,34 -11.3,34 -10.6,34 -9.9,34 -9.2,34 -12.7,34.7 -12,34.7 -11.3,34.7 -10.6,34.7 -9.9,34.7 -9.2,34.7 -12.7,35.4 -12,35.4 -11.3,35.4 -10.6,35.4 -9.9,35.4 -9.2,35.4 -9.9,36.1 -9.2,36.1 -9.9,36.8 -9.2,36.8 18.8,44.6 19.5,44.6 20.2,44.6 19.15,45.15 19.85,45.15
  other v3: 10.775,21.375 11.175,21.375 11.575,21.375 11.975,21.375 12.375,21.375 19.75,21.4 20.15,21.4 20.55,21.4 20.95,21.4 21.35,21.4 28.724,21.388 29.124,21.388 29.524,21.388 29.924,21.388 30.324,21.388 37.7,21.4 38.1,21.4 38.5,21.4 38.9,21.4 39.3,21.4 10.775,21.775 11.175,21.775 11.575,21.775 11.975,21.775 12.375,21.775 28.724,21.788 29.124,21.788 29.524,21.788 29.924,21.788 30.324,21.788 19.75,21.8 20.15,21.8 20.55,21.8 20.95,21.8 21.35,21.8 37.7,21.8 38.1,21.8 38.5,21.8 38.9,21.8 39.3,21.8 10.775,22.175 11.175,22.175 11.575,22.175 11.975,22.175 12.375,22.175 19.75,22.2 20.15,22.2 20.55,22.2 20.95,22.2 21.35,22.2 28.724,22.188 29.124,22.188 29.524,22.188 29.924,22.188 30.324,22.188 37.7,22.2 38.1,22.2 38.5,22.2 38.9,22.2 39.3,22.2 9.575,22.225 9.975,22.225 10.375,22.225 12.775,22.225 13.175,22.225 13.575,22.225 18.55,22.225 18.95,22.225 19.35,22.225 21.75,22.225 22.15,22.225 22.55,22.225 27.525,22.225 27.925,22.225 28.325,22.225 30.725,22.225 31.125,22.225 31.525,22.225 36.5,22.225 36.9,22.225 37.3,22.225 39.7,22.225 40.1,22.225 40.5,22.225 10.775,22.575 11.175,22.575 11.575,22.575 11.975,22.575 12.375,22.575 19.75,22.6 20.15,22.6 20.55,22.6 20.95,22.6 21.35,22.6 28.724,22.588 29.124,22.588 29.524,22.588 29.924,22.588 30.324,22.588 37.7,22.6 38.1,22.6 38.5,22.6 38.9,22.6 39.3,22.6 9.575,22.625 9.975,22.625 10.375,22.625 12.775,22.625 13.175,22.625 13.575,22.625 18.55,22.625 18.95,22.625 19.35,22.625 21.75,22.625 22.15,22.625 22.55,22.625 27.525,22.625 27.925,22.625 28.325,22.625 30.725,22.625 31.125,22.625 31.525,22.625 36.5,22.625 36.9,22.625 37.3,22.625 39.7,22.625 40.1,22.625 40.5,22.625 10.775,22.975 11.175,22.975 11.575,22.975 11.975,22.975 12.375,22.975 19.75,23 20.15,23 20.55,23 20.95,23 21.35,23 28.724,22.988 29.124,22.988 29.524,22.988 29.924,22.988 30.324,22.988 37.7,23 38.1,23 38.5,23 38.9,23 39.3,23 9.575,23.025 9.975,23.025 10.375,23.025 12.775,23.025 13.175,23.025 13.575,23.025 18.55,23.025 18.95,23.025 19.35,23.025 21.75,23.025 22.15,23.025 22.55,23.025 27.525,23.025 27.925,23.025 28.325,23.025 30.725,23.025 31.125,23.025 31.525,23.025 36.5,23.025 36.9,23.025 37.3,23.025 39.7,23.025 40.1,23.025 40.5,23.025 10.775,23.375 11.175,23.375 11.575,23.375 11.975,23.375 12.375,23.375 28.724,23.388 29.124,23.388 29.524,23.388 29.924,23.388 30.324,23.388 19.75,23.4 20.15,23.4 20.55,23.4 20.95,23.4 21.35,23.4 37.7,23.4 38.1,23.4 38.5,23.4 38.9,23.4 39.3,23.4 10.775,23.775 11.175,23.775 11.575,23.775 11.975,23.775 12.375,23.775 19.75,23.8 20.15,23.8 20.55,23.8 20.95,23.8 21.35,23.8 28.724,23.788 29.124,23.788 29.524,23.788 29.924,23.788 30.324,23.788 37.7,23.8 38.1,23.8 38.5,23.8 38.9,23.8 39.3,23.8 10.775,24.175 11.175,24.175 11.575,24.175 11.975,24.175 12.375,24.175 19.75,24.2 20.15,24.2 20.55,24.2 20.95,24.2 21.35,24.2 28.724,24.188 29.124,24.188 29.524,24.188 29.924,24.188 30.324,24.188 37.7,24.2 38.1,24.2 38.5,24.2 38.9,24.2 39.3,24.2 10.775,24.575 11.175,24.575 11.575,24.575 11.975,24.575 12.375,24.575 19.75,24.6 20.15,24.6 20.55,24.6 20.95,24.6 21.35,24.6 28.724,24.588 29.124,24.588 29.524,24.588 29.924,24.588 30.324,24.588 37.7,24.6 38.1,24.6 38.5,24.6 38.9,24.6 39.3,24.6 7.475,24.975 7.875,24.975 8.275,24.975 8.675,24.975 9.075,24.975 10.775,24.975 11.175,24.975 11.575,24.975 11.975,24.975 12.375,24.975 16.45,24.975 16.85,24.975 17.25,24.975 17.65,24.975 18.05,24.975 25.425,24.975 25.825,24.975 26.225,24.975 26.625,24.975 27.025,24.975 28.724,24.988 29.124,24.988 29.524,24.988 29.924,24.988 30.324,24.988 19.75,25 20.15,25 20.55,25 20.95,25 21.35,25 34.4,25 34.8,25 35.2,25 35.6,25 36,25 37.7,25 38.1,25 38.5,25 38.9,25 39.3,25 7.475,25.375 7.875,25.375 8.275,25.375 8.675,25.375 9.075,25.375 16.45,25.375 16.85,25.375 17.25,25.375 17.65,25.375 18.05,25.375 25.425,25.375 25.825,25.375 26.225,25.375 26.625,25.375 27.025,25.375 34.4,25.4 34.8,25.4 35.2,25.4 35.6,25.4 36,25.4 7.475,25.775 7.875,25.775 8.275,25.775 8.675,25.775 9.075,25.775 16.45,25.775 16.85,25.775 17.25,25.775 17.65,25.775 18.05,25.775 25.425,25.775 25.825,25.775 26.225,25.775 26.625,25.775 27.025,25.775 34.4,25.8 34.8,25.8 35.2,25.8 35.6,25.8 36,25.8 7.475,26.175 7.875,26.175 8.275,26.175 8.675,26.175 9.075,26.175 16.45,26.175 16.85,26.175 17.25,26.175 17.65,26.175 18.05,26.175 25.425,26.175 25.825,26.175 26.225,26.175 26.625,26.175 27.025,26.175 34.4,26.2 34.8,26.2 35.2,26.2 35.6,26.2 36,26.2 7.475,26.575 7.875,26.575 8.275,26.575 8.675,26.575 9.075,26.575 16.45,26.575 16.85,26.575 17.25,26.575 17.65,26.575 18.05,26.575 25.425,26.575 25.825,26.575 26.225,26.575 26.625,26.575 27.025,26.575 34.4,26.6 34.8,26.6 35.2,26.6 35.6,26.6 36,26.6 6.275,26.975 6.675,26.975 7.075,26.975 7.475,26.975 7.875,26.975 8.275,26.975 8.675,26.975 9.075,26.975 9.475,26.975 9.875,26.975 10.275,26.975 15.25,26.975 15.65,26.975 16.05,26.975 16.45,26.975 16.85,26.975 17.25,26.975 17.65,26.975 18.05,26.975 18.45,26.975 18.85,26.975 19.25,26.975 24.225,26.975 24.625,26.975 25.025,26.975 25.425,26.975 25.825,26.975 26.225,26.975 26.625,26.975 27.025,26.975 27.425,26.975 27.825,26.975 28.225,26.975 33.2,26.975 33.6,26.975 34,26.975 36.4,26.975 36.8,26.975 37.2,26.975 34.4,27 34.8,27 35.2,27 35.6,27 36,27 6.275,27.375 6.675,27.375 7.075,27.375 7.475,27.375 7.875,27.375 8.275,27.375 8.675,27.375 9.075,27.375 9.475,27.375 9.875,27.375 10.275,27.375 15.25,27.375 15.65,27.375 16.05,27.375 16.45,27.375 16.85,27.375 17.25,27.375 17.65,27.375 18.05,27.375 18.45,27.375 18.85,27.375 19.25,27.375 24.225,27.375 24.625,27.375 25.025,27.375 25.425,27.375 25.825,27.375 26.225,27.375 26.625,27.375 27.025,27.375 27.425,27.375 27.825,27.375 28.225,27.375 33.2,27.375 33.6,27.375 34,27.375 36.4,27.375 36.8,27.375 37.2,27.375 34.4,27.4 34.8,27.4 35.2,27.4 35.6,27.4 36,27.4 6.275,27.775 6.675,27.775 7.075,27.775 7.475,27.775 7.875,27.775 8.275,27.775 8.675,27.775 9.075,27.775 9.475,27.775 9.875,27.775 10.275,27.775 15.25,27.775 15.65,27.775 16.05,27.775 16.45,27.775 16.85,27.775 17.25,27.775 17.65,27.775 18.05,27.775 18.45,27.775 18.85,27.775 19.25,27.775 24.225,27.775 24.625,27.775 25.025,27.775 25.425,27.775 25.825,27.775 26.225,27.775 26.625,27.775 27.025,27.775 27.425,27.775 27.825,27.775 28.225,27.775 33.2,27.775 33.6,27.775 34,27.775 36.4,27.775 36.8,27.775 37.2,27.775 34.4,27.8 34.8,27.8 35.2,27.8 35.6,27.8 36,27.8 7.475,28.175 7.875,28.175 8.275,28.175 8.675,28.175 9.075,28.175 16.45,28.175 16.85,28.175 17.25,28.175 17.65,28.175 18.05,28.175 25.425,28.175 25.825,28.175 26.225,28.175 26.625,28.175 27.025,28.175 34.4,28.2 34.8,28.2 35.2,28.2 35.6,28.2 36,28.2 7.475,28.575 7.875,28.575 8.275,28.575 8.675,28.575 9.075,28.575 16.45,28.575 16.85,28.575 17.25,28.575 17.65,28.575 18.05,28.575 25.425,28.575 25.825,28.575 26.225,28.575 26.625,28.575 27.025,28.575 34.4,28.6 34.8,28.6 35.2,28.6 35.6,28.6 36,28.6
  other v4: 2.6,25 3.3,25 4,25 4.7,25 5.4,25 2.6,27 3.3,27 4,27 4.7,27 5.4,27 2.6,29 3.3,29 4,29 4.7,29 5.4,29
  other v5: 9.7,26.3 10.4,26.3
W: L103.2 TP140.1 X102.0b X102.8 X102.9 X102.10
  other v1: 19.6,27.6 20,27.6 20.4,27.6 20.8,27.6 21.2,27.6 21.6,27.6 22,27.6 22.4,27.6 19.6,28 20,28 20.4,28 20.8,28 21.2,28 21.6,28 22,28 22.4,28 19.6,28.4 20,28.4 20.4,28.4 20.8,28.4 21.2,28.4 21.6,28.4 22,28.4 22.4,28.4 19.6,29.6 20,29.6 20.4,29.6 20.8,29.6 21.2,29.6 21.6,29.6 22,29.6 22.4,29.6 19.6,30 20,30 20.4,30 20.8,30 21.2,30 21.6,30 22,30 22.4,30 19.6,30.4 20,30.4 20.4,30.4 20.8,30.4 21.2,30.4 21.6,30.4 22,30.4 22.4,30.4 19.6,31.6 20,31.6 20.4,31.6 20.8,31.6 21.2,31.6 21.6,31.6 22,31.6 22.4,31.6 19.6,32 20,32 20.4,32 20.8,32 21.2,32 21.6,32 22,32 22.4,32 19.6,32.4 20,32.4 20.4,32.4 20.8,32.4 21.2,32.4 21.6,32.4 22,32.4 22.4,32.4 30.7,34.8 31.1,34.8 31.5,34.8 31.9,34.8 32.3,34.8 32.7,34.8 33.1,34.8 33.5,34.8 33.9,34.8 34.3,34.8 30.7,35.2 31.1,35.2 31.5,35.2 31.9,35.2 32.3,35.2 32.7,35.2 33.1,35.2 33.5,35.2 33.9,35.2 34.3,35.2 30.7,35.6 31.1,35.6 31.5,35.6 31.9,35.6 32.3,35.6 32.7,35.6 33.1,35.6 33.5,35.6 33.9,35.6 34.3,35.6 30.7,36 31.1,36 31.5,36 31.9,36 32.3,36 32.7,36 33.1,36 33.5,36 33.9,36 34.3,36 30.7,36.4 31.1,36.4 31.5,36.4 31.9,36.4 32.3,36.4 32.7,36.4 33.1,36.4 33.5,36.4 33.9,36.4 34.3,36.4 30.7,36.8 31.1,36.8 31.5,36.8 31.9,36.8 32.3,36.8 32.7,36.8 33.1,36.8 33.5,36.8 33.9,36.8 34.3,36.8 30.7,37.2 31.1,37.2 31.5,37.2 31.9,37.2 32.3,37.2 32.7,37.2 33.1,37.2 33.5,37.2 33.9,37.2 34.3,37.2 30.7,37.6 31.1,37.6 31.5,37.6 31.9,37.6 32.3,37.6 32.7,37.6 33.1,37.6 33.5,37.6 33.9,37.6 34.3,37.6 30.7,38 31.1,38 31.5,38 31.9,38 32.3,38 32.7,38 33.1,38 33.5,38 33.9,38 34.3,38 30.7,38.4 31.1,38.4 31.5,38.4 31.9,38.4 32.3,38.4 32.7,38.4 33.1,38.4 33.5,38.4 33.9,38.4 34.3,38.4 30.7,38.8 31.1,38.8 31.5,38.8 31.9,38.8 32.3,38.8 32.7,38.8 33.1,38.8 33.5,38.8 33.9,38.8 34.3,38.8 30.7,39.2 31.1,39.2 31.5,39.2 31.9,39.2 32.3,39.2 32.7,39.2 33.1,39.2 33.5,39.2 33.9,39.2 34.3,39.2
  other v2: 18.8,29 23,29 23.7,29 24.4,29 23.35,29.55 24.05,29.55 24.75,29.55 17.4,29.7 18.1,29.7 18.8,29.7 17.4,31 18.1,31 18.8,31 23,31 23.7,31 24.4,31 25.1,31 27.55,31.05 28.25,31.05 28.95,31.05 29.65,31.05 30.35,31.05 31.05,31.05 31.75,31.05 32.45,31.05 33.15,31.05 33.85,31.05 27.9,31.6 28.6,31.6 29.3,31.6 30,31.6 30.7,31.6 31.4,31.6 32.1,31.6 32.8,31.6 33.5,31.6 28.95,32.15 29.65,32.15 30.35,32.15 31.05,32.15 31.75,32.15 32.45,32.15 29.3,32.7 30,32.7 30.7,32.7 31.4,32.7 32.1,32.7 23,33 29.65,33.25 30.35,33.25 31.05,33.25 31.75,33.25 20.55,33.55 21.25,33.55 21.95,33.55 22.65,33.55 23.35,33.55 29.3,33.8 30,33.8 30.7,33.8 31.4,33.8 32.1,33.8 20.2,34.1 20.9,34.1 21.6,34.1 22.3,34.1 23,34.1 19.85,34.65 20.55,34.65 21.25,34.65 21.95,34.65 22.65,34.65 23.35,34.65 30,35.4 28.6,36.1 29.3,36.1 30,36.1 24.05,36.65 24.75,36.65 25.45,36.65 26.15,36.65 26.85,36.65 27.55,36.65 28.25,36.65 28.95,36.65 23.7,37.2 24.4,37.2 25.1,37.2 25.8,37.2 26.5,37.2 27.2,37.2 27.9,37.2 28.6,37.2 29.3,37.2
  other v4: 19.5,29 20.2,29 20.9,29 21.6,29 22.3,29 19.5,31 20.2,31 20.9,31 21.6,31 22.3,31 20.2,33 20.9,33 21.6,33 22.3,33 30,34.7
pads on no net: FD101.1 FD102.1 FD103.1 FD104.1 MH101.1 MH102.1 MH103.1 MH104.1 STEG101.0 STEG102.0 STEG103.0 STEG104.0 U101.1 X1.0 X3a.0 X3b.0 X4.0 X5.9 X7.0 X8.0 X11.0 X12.0 X13.0 X13.A2 X13.A3 X13.A8 X13.A10 X13.A11 X13.B2 X13.B3 X13.B8 X13.B10 X13.B11 X16.0 X103.0 X104.0 X104.6 X104.7 X104.8

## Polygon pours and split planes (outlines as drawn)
GND on Bottom Side "Bottom-GND" (solid, remove dead copper, pour order 78): 60.2,46 80,46 80,0 60.2,0
GND on Bottom Side "Bottom-GND" (solid, remove dead copper, pour order 65): 8.9,46 16.6,46 16.6,0 0.5,0 0.5,8.1 0.9,8.1 0.9,22.7 12.5,22.7 12.5,26.6 12.4,26.7 8.9,26.7
C_W1 on Bottom Side "Bottom-C_W1" (solid, remove dead copper, pour order 12): 39,15.3 39,0 59.9,0 59.9,15.3
C_W2 on Bottom Side "Bottom-C_W2" (solid, remove dead copper, pour order 11): 39,30.4 39,15.6 59.9,15.6 59.9,30.4
C_W3 on Bottom Side "Bottom-C_W3" (solid, remove dead copper, pour order 10): 39,46 39,30.7 59.9,30.7 59.9,46
SGND on Bottom Side "Bottom_SGND" (solid, remove dead copper, pour order 8): 66.6,0 60.2,0 60.2,3.4 58,3.4 58,5.2 66.1,5.2 66.6,4.7
VP on Bottom Side "VP_L08_P001" (solid, remove dead copper, pour order 1): -13,37.5 -13,23 12.5,23 12.5,25.8 12.8,26.2 12.8,26.9 8.6,26.9 8.6,37.5
U on Bottom Side "Bottom-U" (solid, remove dead copper, pour order 64): 38,15.3 38,0 16.9,0 16.9,18.8 26.1,18.8 26.1,15.3
W on Bottom Side "Bottom_W" (solid, remove dead copper, pour order 61): 38,30.7 38,46 17.1,46 16.9,45.8 16.9,27.2 26.1,27.2 26.1,30.7
SGND on Bottom Side "Bottom-SGND" (solid, remove dead copper, pour order 9): 0,46 0.4,45.6 0.4,41.4 3.2,38.6 8.6,38.6 8.6,46
C_W3 on Bottom Side "Bottom-C_W3" (solid, remove dead copper, pour order 80): 80,17.9 72,17.9 72,29.1 80,29.1
V on Bottom Side "Bottom_V" (solid, remove dead copper, pour order 13): 38,30.4 26.4,30.4 26.4,26.9 16.9,26.9 16.9,19.1 26.4,19.1 26.4,15.6 38,15.6
C_VP on Bottom Side "C_VP_L08_P071" (solid, remove dead copper, pour order 71): -13,8.5 -13,22.7 0.5,22.7 0.5,8.5
GND on Top Side "Top-GND" (solid, remove dead copper, pour order 81): -13.5,46 -13.5,0 80,0 80,46
VP on Top Side "VP_L01_P003" (solid, remove dead copper, pour order 3): -13,37.5 -13,23 7.8,23 7.8,19.5 40.9,19.401 40.9,37.5 7.8,37.5
C_W3 on Top Side "Top-C_W3" (solid, remove dead copper, pour order 2): 80,17.9 72,17.9 72,29.1 80,29.1
C_VP on Top Side "Top-NetF101_1" (solid, remove dead copper, pour order 7): -13,8.5 -13,22.7 0.5,22.7 0.5,8.5
GND on Inner Layer 6 "Mid6-GND" (solid, remove dead copper, pour order 77): 72.9,16.3 80,16.3 80,8 72.9,8
C_W1 on Inner Layer 6 "Bottom-C_W1" (solid, remove dead copper, pour order 15): 39,15.3 39,0 72.6,0 72.6,22.7 64.7,22.7 57.15,15.15
C_W2 on Inner Layer 6 "Bottom-C_W2" (solid, remove dead copper, pour order 14): 39,30.4 39,15.6 57.2,15.6 64.6,23 72.6,23 72.6,27.1 69.3,30.4
VP on Inner Layer 6 "VP_L07_P004" (solid, remove dead copper, pour order 4): -13,37.5 -13,23 16.6,23 16.6,44.3 20.5,44.3 20.5,46 0,46 0,37.5
U on Inner Layer 6 "Bottom-U" (solid, remove dead copper, pour order 31): 38,15.3 38,0 19.8,0 19.8,2 16.9,2 16.9,18.8 26.1,18.8 26.1,15.3
C_W3 on Inner Layer 6 "Bottom-C_W3" (solid, remove dead copper, pour order 16): 39,46 39,30.7 69.4,30.7 72.9,27.2 72.9,16.6 80,16.6 80,46
GND on Inner Layer 6 "Mid6-GND" (solid, remove dead copper, pour order 79): 0.8,22.7 16.6,22.7 16.6,0 0.8,0
W on Inner Layer 6 "Bottom_W" (solid, remove dead copper, pour order 30): 38,30.7 38,46 20.8,46 20.8,44 16.9,44 16.9,27.2 26.1,27.2 26.1,30.7
V on Inner Layer 6 "Bottom_V" (solid, remove dead copper, pour order 29): 38,30.4 26.4,30.4 26.4,26.9 16.9,26.9 16.9,19.1 26.4,19.1 26.4,15.6 38,15.6
C_VP on Inner Layer 6 "C_VP_L07_P062" (solid, remove dead copper, pour order 62): -13,8.5 -13,22.7 0.5,22.7 0.5,8.5
C_W2 on Inner Layer 5 "Bottom-C_W2" (solid, remove dead copper, pour order 17): 39,30.4 39,15.6 57.2,15.6 64.6,23 72.6,23 72.6,27.1 69.3,30.4
GND on Inner Layer 5 "Mid5-GND" (solid, remove dead copper, pour order 76): 73,16.3 80,16.3 80,8 73,8
C_W1 on Inner Layer 5 "Bottom-C_W1" (solid, remove dead copper, pour order 18): 39,15.7 39,0 72.6,0 72.6,22.7 64.7,22.7 57.7,15.7 39.1,15.7
U on Inner Layer 5 "Bottom-U" (solid, remove dead copper, pour order 34): 38,15.7 38,0 19.8,0 19.8,2 16.9,2 16.9,18.8 26.1,18.8 26.1,15.7
VP on Inner Layer 5 "VP_L06_P074" (solid, remove dead copper, pour order 74): -13,37.5 -13,23 0.8,23 0.8,0 19.5,0 19.5,1.7 16.6,1.7 16.6,44.3 20.5,44.3 20.5,46 0,46 0,37.5
C_W3 on Inner Layer 5 "Bottom-C_W3" (solid, remove dead copper, pour order 19): 39,46 39,30.7 69.4,30.7 72.9,27.2 72.9,16.6 80,16.6 80,46
W on Inner Layer 5 "Bottom_W" (solid, remove dead copper, pour order 33): 38,30.3 38,46 20.8,46 20.8,44 16.9,44 16.9,27.2 26.1,27.2 26.1,30.3
V on Inner Layer 5 "Bottom_V" (solid, remove dead copper, pour order 32): 38,30.4 26.4,30.4 26.4,26.9 16.9,26.9 16.9,19.1 26.4,19.1 26.4,15.6 38,15.6
C_VP on Inner Layer 5 "C_VP_L06_P070" (solid, remove dead copper, pour order 70): -13,8.5 -13,22.7 0.5,22.7 0.5,8.5
GND on Inner Layer 4 "Mid3-GND" (solid, remove dead copper, pour order 72): 39,46 39,0 80,0 80,46
C_W2 on Inner Layer 4 "Bottom-C_W2" (solid, remove dead copper, pour order 23): 39,30.4 39,15.6 57.2,15.6 64.6,23 72.6,23 72.6,27.1 69.3,30.4
C_W1 on Inner Layer 4 "Bottom-C_W1" (solid, remove dead copper, pour order 24): 39,15.3 39,0 72.6,0 72.6,22.7 64.7,22.7 57.3,15.3
U on Inner Layer 4 "Bottom-U" (solid, remove dead copper, pour order 49): 38,15.3 38,0 16.9,0 16.9,18.8 26.1,18.8 26.1,15.3
GND on Inner Layer 4 "Mid3-GND" (solid, remove dead copper, pour order 75): -13.5,46 -13.5,0 38,0 38,46
C_W3 on Inner Layer 4 "Bottom-C_W3" (solid, remove dead copper, pour order 25): 39,46 39,30.7 69.4,30.7 72.9,27.2 72.9,16.6 80,16.6 80,46
W on Inner Layer 4 "Bottom_W" (solid, remove dead copper, pour order 48): 38,30.7 38,46 17.1,46 16.9,45.8 16.9,27.2 26.1,27.2 26.1,30.7
V on Inner Layer 4 "Bottom_V" (solid, remove dead copper, pour order 47): 38,30.4 26.4,30.4 26.4,26.9 16.9,26.9 16.9,19.1 26.4,19.1 26.4,15.6 38,15.6
C_VP on Inner Layer 4 "Mid4-C_VP" (solid, remove dead copper, pour order 0): -13,8.5 -13,22.7 0.5,22.7 0.5,8.5
GND on Inner Layer 1 "Mid1-GND" (solid, remove dead copper, pour order 68): -13.5,46 -13.5,0 80,0 80,46
SGND on Inner Layer 1 "Mid1_SGND" (solid, remove dead copper, pour order 60): 0,0 0,7.4 61.9,7.4 61.9,38.6 0,38.6 0,46 80,46 80,0
VP on Inner Layer 1 "VP_L02_P005" (solid, remove dead copper, pour order 5): -13,37.5 -13,23 7.8,23 7.8,19.5 40.9,19.5 40.9,37.5
C_VP on Inner Layer 1 "Top-NetF101_1" (solid, remove dead copper, pour order 63): -13,8.5 -13,22.7 0.5,22.7 0.5,8.5
GND on Inner Layer 3 "Mid3-GND" (solid, remove dead copper, pour order 84): -13.5,46 -13.5,0 80,0 80,46
C_W3 on Inner Layer 3 "Mid3-C_W3" (solid, remove dead copper, pour order 59): 80,17.9 72,17.9 72,29.1 80,29.1
GND on Inner Layer 2 "Mid2-GND" (solid, remove dead copper, pour order 83): -13.5,46 -13.5,0 80,0 80,46
C_W3 on Inner Layer 2 "Mid3-C_W3" (solid, remove dead copper, pour order 69): 80,17.9 72,17.9 72,29.1 80,29.1

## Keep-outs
Keep-Out Layer:
  text "KeepOutLayer" at 87.825,1.814 h1.52

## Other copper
Top Side:
  rectangle net GND: 7.275,35.5 9.275,37.35
  rectangle net GND: 28.525,12.675 30.525,14.6
  rectangle net GND: 37.499,12.65 39.5,14.75
  rectangle net GND: 10.575,12.65 12.575,14.55
  rectangle net GND: 35.35,33.627 37.541,36.05
  rectangle net GND: 24.4,33.6 28,36.1
  rectangle net GND: 15.5,33.825 19,36.1
  text "TopLayer" at 87.825,43.168 h1.52
Inner Layer 1:
  text "MidLayer1" at 87.825,40.142 h1.52
Inner Layer 2:
  text "MidLayer2" at 87.825,37.115 h1.52
Inner Layer 3:
  text "MidLayer3" at 87.825,34.089 h1.52
Inner Layer 6:
  text "MidLayer6" at 87.825,25.01 h1.52
Inner Layer 4:
  text "MidLayer4" at 87.825,31.063 h1.52
Inner Layer 5:
  text "MidLayer5" at 87.825,28.036 h1.52
Bottom Side:
  region net GND: 30.7,42.5 27.7,42.5 27.7,40.5 30.7,40.5
  rectangle net C_S2_Clock_HsDgout1: 75.025,11.65 75.575,11.925
  rectangle net GND: 25.8,39.2 27.7,42.3
  rectangle net GND: 24,3.5 27.7,5.5
  rectangle net VP: 17.5,0.5 21.825,1.7
  rectangle net VP: 20.55,0.5 21.85,4.5
  rectangle net VP: 18.5,41.5 21.8,45.5
  rectangle net GND: 7.1,43.9 7.9,44.4
  rectangle net GND: 6.8,42.8 8.1,44.1
  text "BottomLayer" at 87.825,21.983 h1.52

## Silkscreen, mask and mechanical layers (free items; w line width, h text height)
Top Overlay:
  text "X8" at 43.302,44.022 h2
  text "X7" at 6.402,39.9 h2
  text "X1" at -7.698,35.9 h2
  text "X12" at 58.5,34.302 h2 r90
  text "CANID" at 67.581,32.8 h1.8 r90
  text "X3a" at 43.578,28.502 h2 r90
  text "TopOverlay" at 87.825,18.957 h1.52
  text "X3b" at 79.453,13.702 h2 r90
  text "X11" at 58.5,10.402 h2 r90
  text "X16" at 15.002,10.222 h2
  text "X13" at 68.278,10.102 h2 r90
  text "X2" at 3.902,8.8 h2
  text "X4" at 60.102,7.7 h2
  text "X5" at 43.602,3.222 h2
Bottom Overlay:
  text "BottomOverlay" at 87.825,9.877 h1.52
Top Paste:
  text "TopPaste" at 87.825,12.904 h1.52
Bottom Paste:
  text "Bottom Paste" at 87.825,4.84 h1.52
Top Solder:
  text "TopSolder" at 87.825,15.93 h1.52
  text "'.PCB unassembled'-'.PCB Eng Rev'" at 24.1,1 h0.8
  text "ESCON2" at 33.7,1 h0.8
  text "maxon" at 39.7,1 h0.8
Bottom Solder:
  text "Bottom Solder" at 87.825,7.359 h1.52
Board:
  the board outline again, w0.2
  text "Mechanical1" at 87.825,-0.705 h1.52
Dimensions:
  text "Mechanical2" at 87.825,-3.224 h1.52
Sheet:
  drawing of 26 lines, arcs and shapes, not listed
  text "Mechanical4 (Blattkopf)" at 87.825,-6.25 h1.52
  text "'.Application_BuildNumber'" at 127.146,-30.587 h1.5
  text "PCB P/N" at 167.399,-30.833 h2.5
  text "date:" at 135.2,-31.025 h2
  text "name:" at 150.15,-31.025 h2
  text "created" at 126.675,-33.723 h2
  text "28.09.2022" at 135.075,-33.95 h3
  text "MMAGMHA" at 150.012,-33.95 h3
  text "'.PCB unassembled'-'.PCB Eng Rev'" at 167.725,-35.6 h6
  text "modified" at 126.675,-36.771 h2
  text "12.03.2024" at 135.075,-36.989 h3
  text "MMAGHIN" at 150.012,-36.989 h3
  text "Fabrication Data and Revision" at 167.399,-38.96 h2.5
  text "Date" at 224.301,-38.985 h2.5
  text "reviewed" at 126.675,-39.821 h2
  text "13.03.2024" at 135.075,-40.039 h3
  text "MMAGWAH" at 150.012,-40.039 h3
  text "'.Print_Date'" at 224.801,-41.685 h2.5
  text "CO-no." at 126.775,-43.252 h2.5
  text "'.CO_no'" at 134.575,-43.275 h3
  text "'.Print_Time'" at 224.801,-43.91 h2.5
  text "'.ItemAndRevision'" at 167.725,-44.15 h6
  text "Variant P/N" at 167.401,-48.56 h2.5
  text "'.VariantName'" at 167.487,-52.395 h5.4
  text "File:" at 167.275,-56.575 h2.5
  text ".Department" at 142.95,-56.65 h3
  text "'.Pcb_File_Name_No_Path'" at 171.951,-56.66 h2.5
Mechanical 40:
  text "PCB P/N: '.PCB_raw'" at 30,64 h1.52
  text "'.ItemAndRevision'" at 30,61 h1.52
  text "Variant: '.VariantName'" at 30,58 h1.52
  text "Variant Name: '.Variant_Description'" at 30,55 h1.52
Mechanical 41:
  text "PCB P/N: '.PCB_raw'" at 27,64 h1.52
  text "'.ItemAndRevision'" at 27,61 h1.52
  text "Variant: '.VariantName'" at 27,58 h1.52
  text "Variant Name: '.Variant_Description'" at 27,55 h1.52

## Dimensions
63.85,41.35 to 3.15,39.85 on Dimensions
63.85,41.35 to 63.85,4.65 on Dimensions
0,46 to 0,0 on Dimensions
-13.5,8 to 80,8 on Dimensions
-13.5,8 to 0,9 on Dimensions
67,8 to 0,9 on Dimensions
1,8 to 0,0 on Dimensions
67,8 to 80,8 on Dimensions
